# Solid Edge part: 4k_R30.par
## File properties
Author: Türk
Template: Iso Part.par
Last saved by: Türk
Revision: 5
Application: Solid Edge
Accuracy: 0,990
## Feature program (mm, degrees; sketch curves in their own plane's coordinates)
pattern "PatternOccurrence_1"  XOffset = 9.7297 deg
pattern "PatternOccurrence_2"  XCount = 37; XOffset = 9.7297 deg
pattern "PatternOccurrence_3"  XOffset = 12 deg
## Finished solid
Body 1: solid body, 286 faces, 848 edges, 564 vertices.
  Faces by surface: plane 151, cylinder 135
  Edges by curve: line 578, circle 270
Bounding box of the edges (mm): 67.976 x 35.000 x 67.920, from (-33.9882, -5, -33.9196) to (33.9882, 30, 34).
Cylindrical faces by radius (mm): R1.25 x30, R14 x1, R15 x30, R30 x37, R34 x37
Planar faces by outward normal: +y 1, -y 2, -z 2, oblique 146
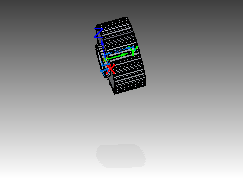
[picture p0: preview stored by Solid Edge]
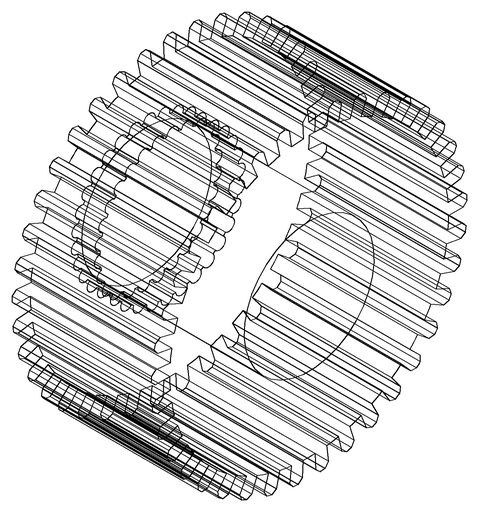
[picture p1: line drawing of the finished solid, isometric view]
